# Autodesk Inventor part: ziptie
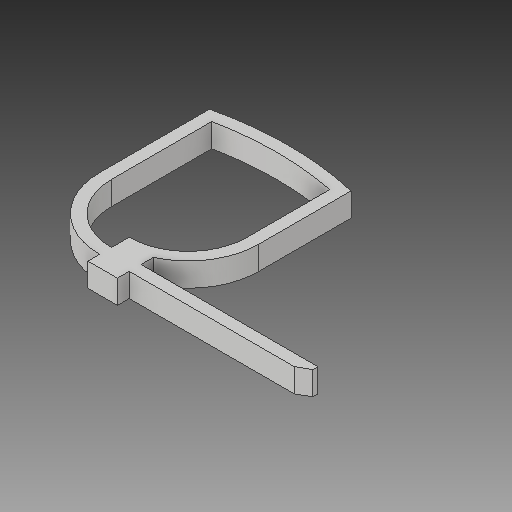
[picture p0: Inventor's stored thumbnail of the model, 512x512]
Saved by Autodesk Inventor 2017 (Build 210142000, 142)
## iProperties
Created: 2020-03
Part Number: ziptie
Material: Generic
Document SubType Name: Modeling
Designer: user
Density: 1 g/cm^3
Appearance: Default
Author: user
Revision Number: ANY
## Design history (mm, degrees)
chamfer "Chamfer1"
body "Solid1"
